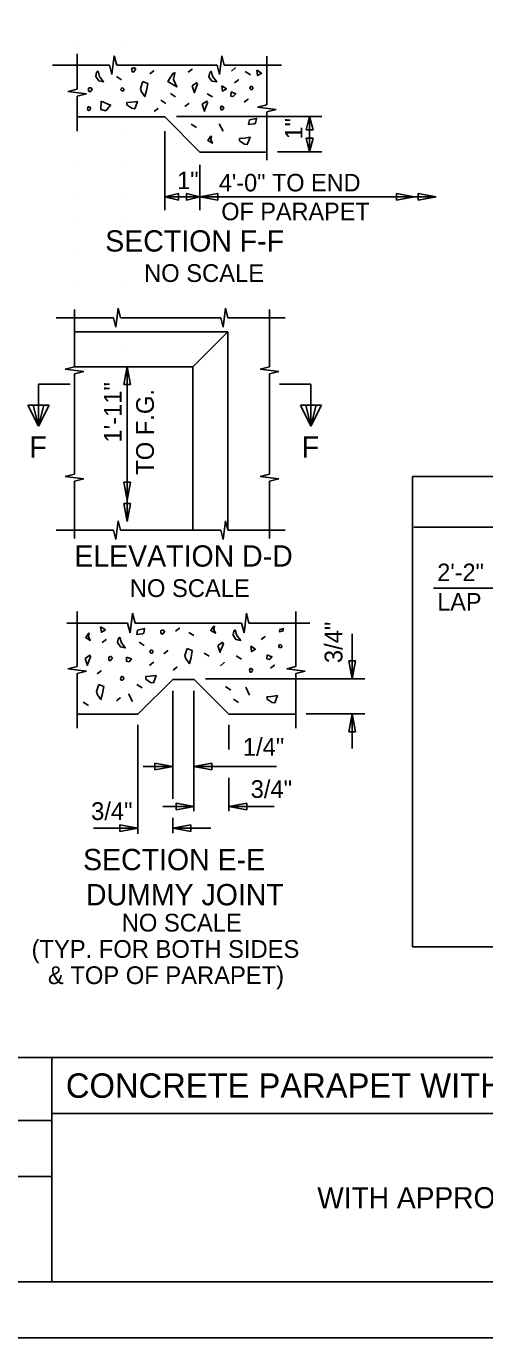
# Model space of a CAD drawing. Extents: x 0 to 34, y 0 to 23.5.
# Drawn here: x 22.02 to 26.11, y 0 to 11.7 of the extents above; entities that cross this region are included whole.
import ezdxf

# ---------------------------------------------------------------- set-up
doc = ezdxf.new("R2010")
doc.units = 0
for name, color, linetype in [('BORDER_ANNO_Cutsheet', 7, 'Continuous'), ('BRDG_ANNO_Anno-Sheet', 7, 'Continuous'), ('BRDG_ANNO_General-Notes', 7, 'Continuous'), ('BRDG_BASE_Active-Point', 7, 'Continuous'), ('BRDG_BASE_Obj-Line', 7, 'Continuous'), ('BRDG_BASE_Pattern', 7, 'Continuous')]:
    doc.layers.add(name, color=color, linetype=linetype)

msp = doc.modelspace()

# ---------------------------------------------------------------- linework, layer by layer
at = {"layer": 'BORDER_ANNO_Cutsheet'}
msp.add_lwpolyline([(0, 22), (34, 22), (34, 0), (0, 0)], close=True, dxfattribs=at)
at = {"layer": 'BRDG_ANNO_Anno-Sheet'}
for p, q in [((19.25, 2.5), (33.5, 2.5)), ((22.25, 0.5), (22.25, 2.5)), ((22.25, 2), (30.25, 2)), ((19.25, 1.938), (22.25, 1.938)), ((19.25, 1.438), (22.25, 1.438))]:
    msp.add_line(p, q, dxfattribs=at)
msp.add_lwpolyline([(1.5, 21.5), (33.5, 21.5), (33.5, 0.5), (1.5, 0.5)], close=True, dxfattribs=at)
at = {"layer": 'BRDG_ANNO_General-Notes'}
for p, q in [((24.657, 10.897), (23.361, 10.897)), ((24.518, 10.777), (24.548, 10.897)), ((24.548, 10.897), (24.548, 10.583)), ((24.548, 10.897), (24.578, 10.777)), ((23.257, 10.062), (23.257, 10.767)), ((24.578, 10.777), (24.518, 10.777)), ((24.518, 10.703), (24.578, 10.703)), ((24.548, 10.583), (24.518, 10.703)), ((24.578, 10.703), (24.548, 10.583)), ((24.26, 10.583), (24.657, 10.583)), ((23.57, 10.062), (23.57, 10.467)), ((23.257, 10.18), (23.377, 10.21)), ((23.377, 10.21), (23.377, 10.15)), ((23.45, 10.15), (23.45, 10.21)), ((23.45, 10.21), (23.57, 10.18)), ((23.57, 10.18), (23.73, 10.21)), ((23.73, 10.21), (23.73, 10.15)), ((25.321, 10.15), (25.321, 10.21)), ((25.321, 10.21), (25.481, 10.18)), ((25.517, 10.15), (25.517, 10.21)), ((25.517, 10.21), (25.677, 10.18)), ((23.57, 10.18), (23.257, 10.18)), ((23.377, 10.15), (23.257, 10.18)), ((23.57, 10.18), (23.45, 10.15)), ((25.677, 10.18), (23.57, 10.18)), ((23.73, 10.15), (23.57, 10.18)), ((25.481, 10.18), (25.321, 10.15)), ((25.677, 10.18), (25.517, 10.15)), ((22.891, 8.505), (22.921, 8.665)), ((22.921, 8.665), (22.921, 7.284)), ((22.921, 8.665), (22.951, 8.505)), ((22.13, 8.51), (22.411, 8.51)), ((22.13, 8.51), (22.13, 8.135)), ((22.951, 8.505), (22.891, 8.505)), ((24.559, 8.51), (24.278, 8.51)), ((24.559, 8.51), (24.559, 8.135)), ((22.13, 8.135), (22.036, 8.323)), ((22.036, 8.323), (22.13, 8.323)), ((22.13, 8.135), (22.083, 8.323)), ((22.13, 8.135), (22.224, 8.323)), ((22.13, 8.135), (22.177, 8.323)), ((22.13, 8.323), (22.224, 8.323)), ((24.559, 8.135), (24.466, 8.323)), ((24.559, 8.323), (24.466, 8.323)), ((24.559, 8.135), (24.513, 8.323)), ((24.559, 8.135), (24.653, 8.323)), ((24.653, 8.323), (24.559, 8.323)), ((24.559, 8.135), (24.606, 8.323)), ((22.891, 7.634), (22.951, 7.634)), ((22.921, 7.474), (22.891, 7.634)), ((22.951, 7.634), (22.921, 7.474)), ((22.891, 7.444), (22.951, 7.444)), ((22.921, 7.284), (22.891, 7.444)), ((22.951, 7.444), (22.921, 7.284)), ((25.651, 6.69), (26.514, 6.69)), ((24.927, 6.281), (24.927, 5.88)), ((24.898, 6.04), (24.957, 6.04)), ((24.927, 5.88), (24.898, 6.04)), ((24.957, 6.04), (24.927, 5.88)), ((25.041, 5.881), (23.619, 5.881)), ((23.328, 4.81), (23.328, 5.774)), ((23.515, 4.698), (23.515, 5.774)), ((23.875, 5.563), (24.082, 5.563)), ((24.518, 5.566), (25.041, 5.566)), ((24.898, 5.406), (24.927, 5.566)), ((24.927, 5.566), (24.927, 5.258)), ((24.927, 5.566), (24.957, 5.406)), ((23.016, 4.497), (23.016, 5.468)), ((23.828, 5.25), (23.828, 5.468)), ((24.957, 5.406), (24.898, 5.406)), ((23.328, 5.098), (23.062, 5.098)), ((23.168, 5.068), (23.168, 5.128)), ((23.168, 5.128), (23.328, 5.098)), ((23.328, 5.098), (23.168, 5.068)), ((23.515, 5.098), (23.675, 5.128)), ((24.253, 5.098), (23.515, 5.098)), ((23.675, 5.068), (23.515, 5.098)), ((23.675, 5.128), (23.675, 5.068)), ((23.828, 4.7), (23.828, 4.996)), ((23.517, 4.741), (23.238, 4.741)), ((23.357, 4.711), (23.357, 4.771)), ((23.357, 4.771), (23.517, 4.741)), ((23.517, 4.741), (23.357, 4.711)), ((23.828, 4.741), (23.988, 4.771)), ((24.232, 4.741), (23.828, 4.741)), ((23.988, 4.711), (23.828, 4.741)), ((23.988, 4.771), (23.988, 4.711)), ((22.856, 4.517), (22.856, 4.577)), ((22.856, 4.577), (23.016, 4.547)), ((23.328, 4.502), (23.328, 4.638)), ((23.328, 4.547), (23.488, 4.577)), ((23.488, 4.577), (23.488, 4.517)), ((23.016, 4.547), (22.62, 4.547)), ((23.016, 4.547), (22.856, 4.517)), ((23.666, 4.547), (23.328, 4.547)), ((23.488, 4.517), (23.328, 4.547))]:
    msp.add_line(p, q, dxfattribs=at)
at = {"layer": 'BRDG_BASE_Active-Point'}
for p, q in [((22.439, 11.567), (22.439, 11.567)), ((22.898, 11.567), (22.898, 11.567)), ((22.439, 11.297), (22.439, 11.297)), ((22.898, 11.297), (22.898, 11.297)), ((22.439, 11.026), (22.439, 11.026)), ((22.898, 11.026), (22.898, 11.026)), ((22.439, 10.755), (22.439, 10.755)), ((22.898, 10.755), (22.898, 10.755)), ((22.439, 10.484), (22.439, 10.484)), ((22.898, 10.484), (22.898, 10.484)), ((22.439, 10.213), (22.439, 10.213)), ((22.898, 10.213), (22.898, 10.213)), ((22.439, 9.942), (22.439, 9.942)), ((22.898, 9.942), (22.898, 9.942)), ((22.439, 9.672), (22.439, 9.672)), ((22.898, 9.672), (22.898, 9.672)), ((22.439, 9.401), (22.439, 9.401)), ((22.898, 9.401), (22.898, 9.401)), ((22.439, 9.13), (22.439, 9.13)), ((22.898, 9.13), (22.898, 9.13)), ((22.439, 8.859), (22.439, 8.859)), ((22.898, 8.859), (22.898, 8.859)), ((22.439, 8.588), (22.439, 8.588)), ((22.898, 8.588), (22.898, 8.588)), ((22.439, 8.317), (22.439, 8.317)), ((22.898, 8.317), (22.898, 8.317)), ((22.439, 8.047), (22.439, 8.047)), ((22.898, 8.047), (22.898, 8.047))]:
    msp.add_line(p, q, dxfattribs=at)
at = {"layer": 'BRDG_BASE_Obj-Line'}
for p, q in [((22.764, 11.356), (22.254, 11.356)), ((22.474, 11.457), (22.474, 11.142)), ((22.764, 11.356), (22.785, 11.273)), ((22.785, 11.273), (22.806, 11.44)), ((22.806, 11.44), (22.827, 11.356)), ((23.723, 11.356), (22.827, 11.356)), ((23.723, 11.356), (23.744, 11.273)), ((23.744, 11.273), (23.764, 11.44)), ((23.764, 11.44), (23.785, 11.356)), ((24.296, 11.356), (23.785, 11.356)), ((24.165, 11.435), (24.165, 11.001)), ((22.391, 11.121), (22.474, 11.142)), ((22.557, 11.1), (22.391, 11.121)), ((22.474, 11.079), (22.557, 11.1)), ((22.474, 11.079), (22.474, 10.767)), ((24.082, 10.981), (24.165, 11.001)), ((22.474, 10.893), (23.257, 10.893)), ((23.57, 10.58), (23.257, 10.893)), ((24.249, 10.96), (24.082, 10.981)), ((24.165, 10.939), (24.249, 10.96)), ((24.165, 10.939), (24.165, 10.509)), ((23.57, 10.58), (24.165, 10.58)), ((22.45, 9.175), (22.45, 8.665)), ((22.819, 9.019), (22.84, 9.186)), ((22.84, 9.186), (22.86, 9.102)), ((23.777, 9.019), (23.798, 9.186)), ((23.798, 9.186), (23.819, 9.102)), ((24.19, 9.175), (24.19, 8.665)), ((22.798, 9.102), (22.288, 9.102)), ((22.798, 9.102), (22.819, 9.019)), ((23.756, 9.102), (22.86, 9.102)), ((23.756, 9.102), (23.777, 9.019)), ((24.329, 9.102), (23.819, 9.102)), ((22.45, 8.977), (23.819, 8.977)), ((23.506, 8.665), (23.819, 8.977)), ((23.819, 8.977), (23.819, 7.205)), ((22.367, 8.644), (22.45, 8.665)), ((22.45, 8.665), (23.506, 8.665)), ((23.506, 8.665), (23.506, 7.205)), ((24.107, 8.644), (24.19, 8.665)), ((22.533, 8.623), (22.367, 8.644)), ((22.45, 8.602), (22.533, 8.623)), ((22.45, 8.602), (22.45, 7.706)), ((24.274, 8.623), (24.107, 8.644)), ((24.19, 8.602), (24.274, 8.623)), ((24.19, 8.602), (24.19, 7.706)), ((22.367, 7.686), (22.45, 7.706)), ((22.533, 7.665), (22.367, 7.686)), ((22.45, 7.644), (22.533, 7.665)), ((22.45, 7.644), (22.45, 7.133)), ((24.107, 7.686), (24.19, 7.706)), ((24.274, 7.665), (24.107, 7.686)), ((24.19, 7.644), (24.274, 7.665)), ((24.19, 7.644), (24.19, 7.133)), ((25.464, 3.489), (25.464, 7.685)), ((25.464, 7.685), (33.071, 7.685)), ((22.819, 7.122), (22.84, 7.289)), ((22.84, 7.289), (22.86, 7.205)), ((23.777, 7.122), (23.798, 7.289)), ((23.798, 7.289), (23.819, 7.205)), ((22.798, 7.205), (22.288, 7.205)), ((22.798, 7.205), (22.819, 7.122)), ((23.756, 7.205), (22.86, 7.205)), ((23.756, 7.205), (23.777, 7.122)), ((24.329, 7.205), (23.819, 7.205)), ((25.476, 7.234), (33.066, 7.234)), ((22.474, 6.48), (22.474, 5.99)), ((22.946, 6.289), (22.968, 6.466)), ((22.968, 6.466), (22.991, 6.377)), ((23.963, 6.289), (23.985, 6.466)), ((23.985, 6.466), (24.007, 6.377)), ((24.426, 6.48), (24.426, 5.99)), ((22.924, 6.377), (22.383, 6.377)), ((22.924, 6.377), (22.946, 6.289)), ((23.941, 6.377), (22.991, 6.377)), ((23.941, 6.377), (23.963, 6.289)), ((24.549, 6.377), (24.007, 6.377)), ((22.391, 5.969), (22.474, 5.99)), ((22.557, 5.949), (22.391, 5.969)), ((24.343, 5.969), (24.426, 5.99)), ((24.509, 5.949), (24.343, 5.969)), ((22.474, 5.928), (22.557, 5.949)), ((22.474, 5.928), (22.474, 5.438)), ((23.016, 5.563), (23.328, 5.875)), ((23.328, 5.875), (23.515, 5.875)), ((23.828, 5.563), (23.515, 5.876)), ((24.426, 5.928), (24.509, 5.949)), ((24.426, 5.928), (24.426, 5.438)), ((22.471, 5.563), (23.016, 5.563)), ((23.828, 5.563), (24.423, 5.563)), ((25.464, 3.489), (33.071, 3.489))]:
    msp.add_line(p, q, dxfattribs=at)
at = {"layer": 'BRDG_BASE_Pattern'}
for p, q in [((22.824, 11.254), (22.871, 11.225)), ((23.974, 11.299), (24.02, 11.27)), ((23.22, 11.042), (23.266, 11.013)), ((23.306, 11.102), (23.353, 11.073)), ((23.635, 11.101), (23.682, 11.072)), ((23.492, 10.829), (23.538, 10.8)), ((23.741, 10.833), (23.776, 10.765)), ((23.027, 6.206), (23.073, 6.176)), ((23.47, 6.294), (23.516, 6.265)), ((23.607, 6.11), (23.653, 6.081)), ((23.894, 6.084), (23.94, 6.055)), ((22.933, 5.747), (22.967, 5.678)), ((23.007, 5.829), (23.053, 5.8)), ((23.797, 5.81), (23.844, 5.78)), ((23.978, 5.804), (24.012, 5.735)), ((22.529, 5.67), (22.575, 5.641)), ((23.868, 5.698), (23.914, 5.668))]:
    msp.add_line(p, q, dxfattribs=at)
for points in [[(22.648, 11.293), (22.641, 11.255), (22.667, 11.217), (22.71, 11.208), (22.675, 11.254), (22.661, 11.301)], [(22.963, 11.328), (22.963, 11.302), (22.975, 11.294), (22.979, 11.297), (22.989, 11.308), (22.996, 11.322), (22.991, 11.328), (22.984, 11.332), (22.98, 11.332), (22.974, 11.33)], [(23.122, 11.278), (23.157, 11.305)], [(23.33, 11.283), (23.282, 11.211), (23.363, 11.162), (23.334, 11.228), (23.346, 11.288)], [(23.466, 11.294), (23.5, 11.321)], [(23.658, 11.291), (23.65, 11.252), (23.676, 11.214), (23.719, 11.206), (23.685, 11.251), (23.67, 11.299)], [(23.85, 11.303), (23.885, 11.331)], [(24.077, 11.311), (24.084, 11.262), (24.119, 11.283)], [(22.576, 11.151), (22.576, 11.125), (22.588, 11.116), (22.591, 11.12), (22.601, 11.13), (22.608, 11.144), (22.603, 11.151), (22.596, 11.154), (22.593, 11.154), (22.586, 11.152)], [(22.872, 11.154), (22.864, 11.135), (22.874, 11.125), (22.886, 11.125), (22.892, 11.13), (22.892, 11.14), (22.89, 11.145), (22.884, 11.151)], [(23.059, 11.209), (23.038, 11.147), (23.049, 11.116), (23.079, 11.075), (23.093, 11.13), (23.104, 11.192)], [(23.499, 11.171), (23.52, 11.109), (23.52, 11.116), (23.547, 11.185), (23.54, 11.198)], [(23.765, 11.171), (23.772, 11.123), (23.806, 11.144)], [(23.879, 11.198), (23.913, 11.225)], [(24.022, 11.167), (24.013, 11.148), (24.023, 11.138), (24.036, 11.138), (24.041, 11.143), (24.041, 11.154), (24.039, 11.159), (24.034, 11.164)], [(22.688, 11.034), (22.685, 10.96), (22.73, 10.949), (22.773, 10.999)], [(22.96, 11.026), (22.919, 11.022), (22.919, 11.001), (22.963, 10.971), (22.988, 10.967), (23.012, 11.032)], [(23.435, 10.986), (23.469, 11.014)], [(23.59, 11.006), (23.611, 10.944), (23.611, 10.951), (23.638, 11.02), (23.632, 11.034)], [(23.847, 11.117), (23.845, 11.08), (23.867, 11.075), (23.889, 11.1)], [(23.964, 11.025), (23.999, 11.053)], [(22.567, 10.969), (22.572, 10.952), (22.577, 10.952), (22.584, 10.953), (22.59, 10.958), (22.595, 10.969), (22.593, 10.979), (22.584, 10.981), (22.581, 10.984), (22.574, 10.984)], [(23.161, 10.941), (23.195, 10.968)], [(23.753, 10.973), (23.759, 10.956), (23.764, 10.956), (23.771, 10.958), (23.776, 10.963), (23.781, 10.973), (23.779, 10.984), (23.771, 10.985), (23.767, 10.989), (23.76, 10.989)], [(24.011, 10.867), (24.004, 10.825), (24.052, 10.832), (24.066, 10.839), (24.073, 10.88)], [(23.665, 10.718), (23.641, 10.682), (23.681, 10.658), (23.666, 10.691), (23.672, 10.721)], [(23.964, 10.705), (23.923, 10.702), (23.923, 10.681), (23.967, 10.65), (23.992, 10.647), (24.016, 10.712)], [(22.684, 6.344), (22.691, 6.296), (22.726, 6.316)], [(23.013, 6.315), (23.006, 6.274), (23.054, 6.281), (23.068, 6.288), (23.075, 6.329)], [(23.352, 6.306), (23.387, 6.333)], [(23.69, 6.346), (23.666, 6.31), (23.707, 6.286), (23.692, 6.319), (23.698, 6.349)], [(24.283, 6.321), (24.279, 6.3), (24.303, 6.304), (24.31, 6.307), (24.314, 6.328)], [(22.575, 6.284), (22.551, 6.248), (22.592, 6.223), (22.577, 6.256), (22.583, 6.286)], [(22.699, 6.205), (22.733, 6.232)], [(22.842, 6.242), (22.834, 6.203), (22.86, 6.165), (22.903, 6.156), (22.869, 6.202), (22.854, 6.249)], [(23.221, 6.312), (23.221, 6.286), (23.233, 6.277), (23.237, 6.281), (23.247, 6.291), (23.254, 6.305), (23.249, 6.312), (23.242, 6.315), (23.239, 6.315), (23.232, 6.313)], [(23.73, 6.178), (23.751, 6.116), (23.751, 6.123), (23.779, 6.192), (23.772, 6.205)], [(23.873, 6.307), (23.866, 6.268), (23.891, 6.23), (23.934, 6.222), (23.9, 6.267), (23.885, 6.315)], [(24.117, 6.23), (24.151, 6.258)], [(22.546, 6.062), (22.567, 6), (22.567, 6.007), (22.595, 6.076), (22.588, 6.09)], [(23.131, 6.138), (23.122, 6.119), (23.132, 6.108), (23.144, 6.108), (23.15, 6.114), (23.15, 6.124), (23.148, 6.129), (23.143, 6.134)], [(23.249, 6.103), (23.283, 6.131)], [(23.455, 6.151), (23.435, 6.089), (23.445, 6.058), (23.476, 6.016), (23.49, 6.071), (23.5, 6.133)], [(24.023, 6.171), (24.03, 6.123), (24.064, 6.144)], [(24.169, 6.094), (24.167, 6.057), (24.19, 6.052), (24.211, 6.077)], [(24.28, 6.187), (24.271, 6.168), (24.282, 6.158), (24.294, 6.158), (24.299, 6.163), (24.299, 6.173), (24.297, 6.178), (24.292, 6.184)], [(22.756, 6.074), (22.756, 6.048), (22.768, 6.04), (22.772, 6.043), (22.782, 6.054), (22.789, 6.067), (22.784, 6.074), (22.777, 6.078), (22.773, 6.078), (22.767, 6.076)], [(22.916, 6.074), (22.914, 6.037), (22.937, 6.032), (22.958, 6.057)], [(23.121, 5.999), (23.155, 6.027)], [(23.33, 5.957), (23.364, 5.984)], [(23.752, 5.996), (23.786, 6.024)], [(24.012, 5.957), (24.017, 5.94), (24.022, 5.94), (24.029, 5.941), (24.034, 5.946), (24.039, 5.957), (24.038, 5.967), (24.029, 5.969), (24.025, 5.972), (24.018, 5.972)], [(24.198, 5.976), (24.233, 6.003)], [(22.654, 5.924), (22.688, 5.952)], [(22.862, 5.884), (22.868, 5.867), (22.873, 5.867), (22.879, 5.869), (22.885, 5.874), (22.89, 5.884), (22.888, 5.895), (22.879, 5.897), (22.876, 5.9), (22.869, 5.9)], [(23.127, 5.902), (23.086, 5.899), (23.086, 5.878), (23.13, 5.847), (23.155, 5.844), (23.179, 5.909)], [(22.667, 5.829), (22.646, 5.767), (22.656, 5.736), (22.687, 5.695), (22.701, 5.75), (22.711, 5.812)], [(22.825, 5.682), (22.859, 5.709)], [(24.209, 5.723), (24.168, 5.72), (24.168, 5.699), (24.213, 5.668), (24.237, 5.665), (24.261, 5.73)]]:
    msp.add_lwpolyline(points, close=True, dxfattribs=at)

# ---------------------------------------------------------------- texts
at = {"layer": 'BRDG_ANNO_Anno-Sheet'}
for s, height, p in [('CONCRETE PARAPET WITH THRIE BEAM RAIL', 0.21813, (22.374, 2.141)), ('WITH APPROACH SLAB', 0.1875, (24.616, 1.156))]:
    msp.add_text(s, height=height, dxfattribs=at).set_placement(p)
at = {"layer": 'BRDG_ANNO_General-Notes'}
for s, height, rotation, p in [('1"', 0.1562, 90.0077, (24.484, 10.693)), ('1"', 0.1562, 0.0077, (23.367, 10.249)), ('1\'-11"', 0.1583, 90, (22.872, 7.988)), ('TO F.G.', 0.1583, 90, (23.159, 7.701)), ('3/4"', 0.1583, 90.011, (24.84, 6.02)), ('1/4"', 0.1583, 0.011, (23.952, 5.193)), ('3/4"', 0.1583, 0.011, (24.022, 4.817))]:
    msp.add_text(s, height=height, rotation=rotation, dxfattribs=at).set_placement(p)
for s, height, p in [('4\'-0" TO END', 0.15625, (23.738, 10.229)), ('OF PARAPET', 0.1562, (23.76, 9.972)), ('SECTION F-F', 0.19, (22.725, 9.692)), ('NO SCALE', 0.1583, (23.071, 9.421)), ('F', 0.188, (22.049, 7.854)), ('F', 0.188, (24.478, 7.854)), ('ELEVATION D-D', 0.19, (22.449, 6.881)), ('2\'-2"', 0.1562, (25.686, 6.752)), ('NO SCALE', 0.1583, (22.944, 6.61)), ('LAP', 0.1562, (25.686, 6.489)), ('3/4"', 0.1583, (22.599, 4.62)), ('SECTION E-E', 0.19, (22.527, 4.172)), ('DUMMY JOINT', 0.19, (22.553, 3.859)), ('NO SCALE', 0.1583, (22.872, 3.625)), ('(TYP. FOR BOTH SIDES', 0.15833, (22.068, 3.39)), ('& TOP OF PARAPET)', 0.15833, (22.214, 3.156))]:
    msp.add_text(s, height=height, dxfattribs=at).set_placement(p)

doc.saveas('drawing.dxf')
